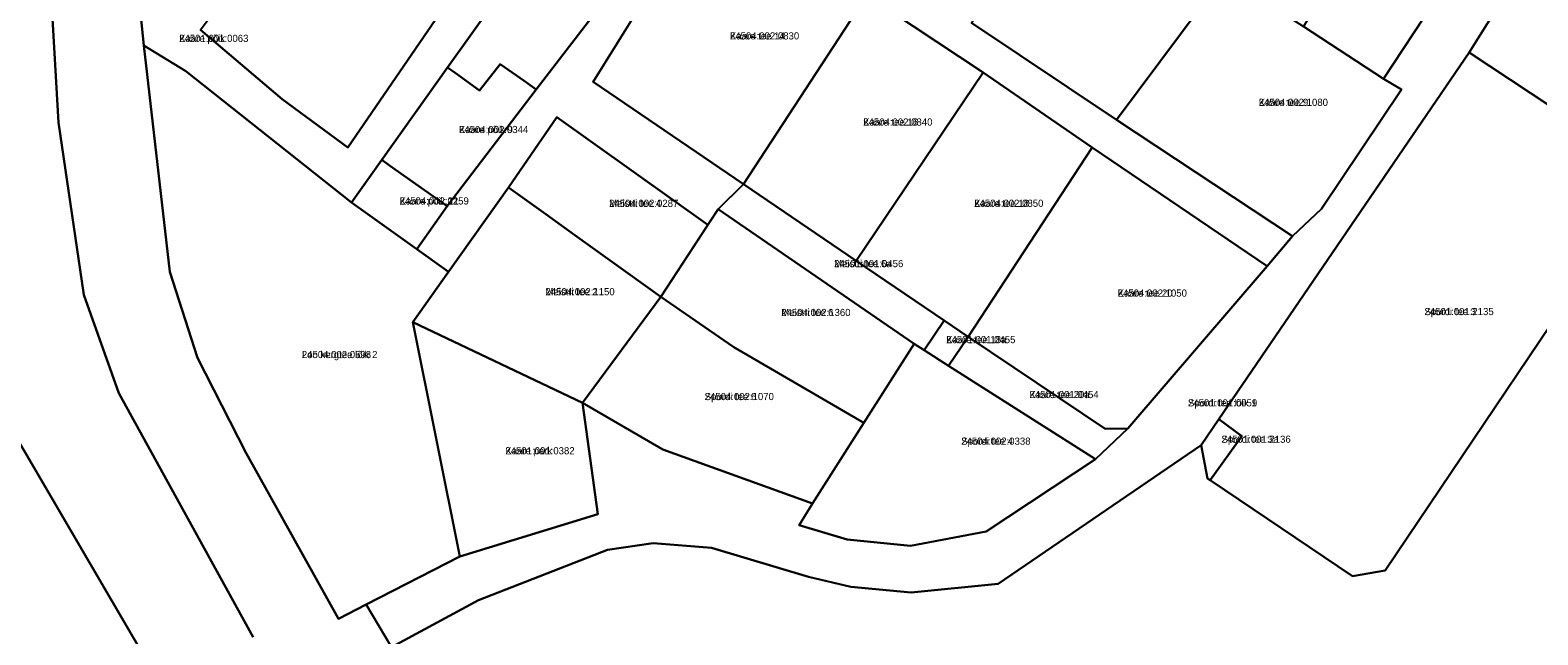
# Model space of a CAD drawing. Extents: x 551291 to 575799, y 6581704 to 6610137.
# Drawn here: x 553257.5 to 553573.3, y 6588636.2 to 6588762.8 of the extents above; entities that cross this region are included whole.
import ezdxf

# ---------------------------------------------------------------- set-up
doc = ezdxf.new("R2010")
doc.units = 0
for name, color, linetype in [('L_AADRESS', 7, 'Continuous'), ('PIIR', 7, 'Continuous'), ('TUNNUS', 7, 'Continuous')]:
    doc.layers.add(name, color=color, linetype=linetype)

msp = doc.modelspace()

# ---------------------------------------------------------------- linework, layer by layer
at = {"layer": 'PIIR'}
for points in [[(553306.96, 6589241.42), (553418.75, 6589107.11), (553465.1, 6589057.77), (553426.41, 6589023.65), (553416.94, 6589023.42), (553405.24, 6589006.54), (553386.47, 6588978.82), (553366.97, 6588950.29), (553347.5, 6588922.26), (553328.32, 6588893.48), (553310.97, 6588866.48), (553295.9, 6588840.93), (553293.3, 6588836.47), (553284.25, 6588808.2), (553281.37, 6588788.28), (553279.94, 6588773.2), (553281.34, 6588759.56), (553286.75, 6588712.18), (553292.54, 6588694.23), (553302.76, 6588674.21), (553322.1, 6588639.57), (553327.9, 6588642.55), (553333.21, 6588633.65)], [(553304.25, 6588635.73), (553276.09, 6588686.81), (553268.73, 6588707.38), (553263.45, 6588743.45), (553261.61, 6588774.94), (553261.53, 6588779.69), (553268.25, 6588819.66), (553275.1, 6588838.43), (553306.34, 6588891.77), (553312.93, 6588901.87), (553404.2, 6589032.89), (553408.34, 6589040.49), (553410.17, 6589044.79), (553406.72, 6589048.87), (553402.28, 6589051.83), (553400.8, 6589049.61), (553398.49, 6589073.95), (553395.53, 6589101.85), (553384.69, 6589115.08), (553365.54, 6589138.04), (553346.66, 6589161.17), (553325.86, 6589186.24), (553304.84, 6589211.6), (553283.11, 6589237.87)], [(553283.84, 6588627.54), (552961.52, 6589179.1), (552977.35, 6589194.37), (552972.63, 6589227.51)], [(552987.46, 6589221.09), (552996.13, 6589179.71), (553015.61, 6589144.56), (553032.97, 6589119.27), (553044.81, 6589101.34), (553061.59, 6589069.5), (553081.67, 6589036.33), (553098.19, 6589009.03), (553115.45, 6588981.63), (553133.28, 6588953.24), (553151.85, 6588924.7), (553154, 6588914.4), (553168.49, 6588890.04), (553200.1, 6588836.89), (553225.39, 6588797.38), (553242.99, 6588767.77), (553261.61, 6588774.94), (553263.45, 6588743.45), (553268.73, 6588707.38), (553276.09, 6588686.81), (553304.25, 6588635.73)], [(553586.81, 6588802.61), (553558.93, 6588758.15), (553506.49, 6588681.35), (553502.8, 6588675.9), (553460.27, 6588646.9), (553442.05, 6588645.08), (553429.4, 6588646.23), (553420.55, 6588648.38), (553400.24, 6588654.46), (553388, 6588655.43), (553378.43, 6588653.99), (553351.43, 6588643.46), (553333.21, 6588633.65), (553327.9, 6588642.55), (553347.5, 6588652.63), (553376.4, 6588661.49), (553373.17, 6588684.76), (553390, 6588675.01), (553421.37, 6588663.69), (553418.57, 6588659.2), (553428.61, 6588656.17), (553441.9, 6588654.88), (553457.72, 6588657.87), (553480.66, 6588672.97), (553487.45, 6588679.44), (553516.62, 6588713.38), (553521.94, 6588719.68), (553527.99, 6588725.41), (553544.73, 6588750.38), (553540.98, 6588752.6), (553572.58, 6588800.64)], [(553400.19, 6588791.84), (553375.41, 6588751.96), (553406.91, 6588730.55), (553401.61, 6588725.29), (553399.46, 6588722.05), (553367.85, 6588744.61), (553357.7, 6588729.84), (553345.15, 6588712.18), (553338.5, 6588716.94), (553344.85, 6588725.98), (553363.5, 6588750.35), (553377.97, 6588769.25)], [(553362.84, 6588780.12), (553344.93, 6588754.96), (553331.19, 6588735.66), (553324.82, 6588726.72), (553290.15, 6588754.19), (553281.34, 6588759.56), (553279.94, 6588773.2)], [(553293.22, 6588762.88), (553310.27, 6588748.34), (553324.04, 6588738.25), (553344.91, 6588768.66)], [(553454.68, 6588764.35), (553485.08, 6588744.02), (553521.94, 6588719.68), (553516.62, 6588713.38), (553479.95, 6588738.26), (553457.1, 6588753.9), (553432.77, 6588770.1)], [(553333.21, 6588633.65), (553351.43, 6588643.46), (553378.43, 6588653.99), (553388, 6588655.43), (553400.24, 6588654.46), (553420.55, 6588648.38), (553429.4, 6588646.23), (553442.05, 6588645.08), (553460.27, 6588646.9), (553502.8, 6588675.9), (553504.14, 6588668.94), (553504.66, 6588668.6), (553534.5, 6588648.5), (553541.34, 6588649.66), (553594.45, 6588728.54)]]:
    msp.add_lwpolyline(points, dxfattribs=at)
for points in [[(552921.6, 6588881.7), (552784.14, 6588949.64), (552783.95, 6588954.96), (552919.59, 6589073.28), (552917.17, 6589074.68), (552877.21, 6589097.76), (552961.52, 6589179.1), (553283.84, 6588627.54), (553249.24, 6588613.65), (553242.74, 6588611.05), (553050.97, 6588792.92), (552970.24, 6588851.09)], [(553572.58, 6588800.64), (553540.98, 6588752.6), (553524.22, 6588763.56), (553555.41, 6588811.64)], [(553586.81, 6588802.61), (553623.3, 6588779.03), (553593.12, 6588735.52), (553558.93, 6588758.15)], [(553485.08, 6588744.02), (553454.68, 6588764.35), (553475.29, 6588795.15), (553494.29, 6588783.09), (553507.53, 6588774.2)], [(553432.77, 6588770.1), (553406.91, 6588730.55), (553375.41, 6588751.96), (553400.19, 6588791.84)], [(553344.91, 6588768.66), (553324.04, 6588738.25), (553310.27, 6588748.34), (553293.22, 6588762.88), (553312.85, 6588789.54)], [(553362.84, 6588780.12), (553364.44, 6588778.96), (553374.81, 6588771.64), (553377.97, 6588769.25), (553363.5, 6588750.35), (553360.96, 6588752.16), (553355.97, 6588755.7), (553351.65, 6588750.19), (553346.52, 6588753.84), (553344.93, 6588754.96)], [(553507.53, 6588774.2), (553511.71, 6588771.65), (553524.22, 6588763.56), (553540.98, 6588752.6), (553544.73, 6588750.38), (553527.99, 6588725.41), (553521.94, 6588719.68), (553485.08, 6588744.02)], [(553406.91, 6588730.55), (553432.77, 6588770.1), (553457.1, 6588753.9), (553430.53, 6588714.52)], [(553281.34, 6588759.56), (553290.15, 6588754.19), (553324.82, 6588726.72), (553338.5, 6588716.94), (553345.15, 6588712.18), (553337.7, 6588701.66), (553347.5, 6588652.63), (553327.9, 6588642.55), (553322.1, 6588639.57), (553302.76, 6588674.21), (553292.54, 6588694.23), (553286.75, 6588712.18)], [(553506.49, 6588681.35), (553558.93, 6588758.15), (553593.12, 6588735.52), (553590.28, 6588731.33), (553594.45, 6588728.54), (553541.34, 6588649.66), (553534.5, 6588648.5), (553504.66, 6588668.6), (553511.28, 6588677.78)], [(553344.93, 6588754.96), (553346.52, 6588753.84), (553351.65, 6588750.19), (553355.97, 6588755.7), (553360.96, 6588752.16), (553363.5, 6588750.35), (553344.85, 6588725.98), (553343.16, 6588727.12), (553332.81, 6588734.49), (553331.19, 6588735.66)], [(553430.53, 6588714.52), (553457.1, 6588753.9), (553479.95, 6588738.26), (553453.99, 6588698.57), (553448.93, 6588701.99)], [(553357.7, 6588729.84), (553367.85, 6588744.61), (553399.46, 6588722.05), (553389.6, 6588707), (553371.6, 6588719.9), (553365.5, 6588724.27)], [(553453.99, 6588698.57), (553479.95, 6588738.26), (553516.62, 6588713.38), (553487.45, 6588679.44), (553482.71, 6588679.35)], [(553324.82, 6588726.72), (553331.19, 6588735.66), (553332.81, 6588734.49), (553343.16, 6588727.12), (553344.85, 6588725.98), (553338.5, 6588716.94)], [(553337.7, 6588701.66), (553345.15, 6588712.18), (553357.7, 6588729.84), (553365.5, 6588724.27), (553371.6, 6588719.9), (553389.6, 6588707), (553373.17, 6588684.76)], [(553442.7, 6588697.14), (553401.61, 6588725.29), (553406.91, 6588730.55), (553430.53, 6588714.52), (553448.93, 6588701.99), (553444.77, 6588695.8)], [(553442.7, 6588697.14), (553432.13, 6588680.61), (553404.91, 6588696.43), (553389.6, 6588707), (553401.61, 6588725.29)], [(553404.91, 6588696.43), (553432.13, 6588680.61), (553421.37, 6588663.69), (553390, 6588675.01), (553373.17, 6588684.76), (553389.6, 6588707)], [(553376.4, 6588661.49), (553347.5, 6588652.63), (553337.7, 6588701.66), (553373.17, 6588684.76)], [(553444.77, 6588695.8), (553448.93, 6588701.99), (553453.99, 6588698.57), (553449.89, 6588692.53)], [(553442.7, 6588697.14), (553444.77, 6588695.8), (553449.89, 6588692.53), (553480.66, 6588672.97), (553457.72, 6588657.87), (553441.9, 6588654.88), (553428.61, 6588656.17), (553418.57, 6588659.2), (553421.37, 6588663.69), (553432.13, 6588680.61)], [(553449.89, 6588692.53), (553453.99, 6588698.57), (553482.71, 6588679.35), (553487.45, 6588679.44), (553480.66, 6588672.97)], [(553502.8, 6588675.9), (553506.49, 6588681.35), (553511.28, 6588677.78), (553504.66, 6588668.6), (553504.14, 6588668.94)]]:
    msp.add_lwpolyline(points, close=True, dxfattribs=at)

# ---------------------------------------------------------------- texts
at = {"layer": 'L_AADRESS'}
for s, p in [('Kaare tee 14', (553404.09, 6588760.85)), ('Kaare põik', (553288.73, 6588760.33)), ('Kaare tee 9', (553514.84, 6588746.94)), ('Kaare tee 16', (553432, 6588742.82)), ('Kaare põik 9', (553347.34, 6588741.25)), ('Kaare põik 11', (553334.89, 6588726.3)), ('Meistri tee 4', (553378.77, 6588725.8)), ('Kaare tee 18', (553455.24, 6588725.81)), ('Meistri tee 6a', (553425.9, 6588713.18)), ('Meistri tee 2', (553365.44, 6588707.3)), ('Kaare tee 20', (553485.3, 6588707.01)), ('Meistri tee 6', (553414.84, 6588702.95)), ('Spordi tee 3', (553549.55, 6588703.14)), ('Kaare tee 18a', (553449.38, 6588697.27)), ('Loo kergtee lõik 2', (553314.42, 6588694.14)), ('Spordi tee 6', (553398.79, 6588685.35)), ('Kaare tee 20a', (553466.82, 6588685.77)), ('Spordi tee lõik 1', (553500.02, 6588684.03)), ('Spordi tee 4', (553452.54, 6588676.01)), ('Spordi tee 3a', (553507.04, 6588676.42)), ('Kaare park', (553357.05, 6588674))]:
    msp.add_text(s, height=1.5, dxfattribs=at).set_placement(p)
at = {"layer": 'TUNNUS'}
for s, p in [('24504:002:0830', (553404.09, 6588760.85)), ('24501:001:0063', (553288.73, 6588760.33)), ('24504:002:1080', (553514.84, 6588746.94)), ('24504:002:0840', (553432, 6588742.82)), ('24504:002:0344', (553347.34, 6588741.25)), ('24504:002:0259', (553334.89, 6588726.3)), ('24504:002:0287', (553378.77, 6588725.8)), ('24504:002:0850', (553455.24, 6588725.81)), ('24501:001:0456', (553425.9, 6588713.18)), ('24504:002:1150', (553365.44, 6588707.3)), ('24504:002:1050', (553485.3, 6588707.01)), ('24504:002:1360', (553414.84, 6588702.95)), ('24501:001:2135', (553549.55, 6588703.14)), ('24501:001:0455', (553449.38, 6588697.27)), ('24504:002:0598', (553314.42, 6588694.14)), ('24504:002:1070', (553398.79, 6588685.35)), ('24501:001:0454', (553466.82, 6588685.77)), ('24501:001:0059', (553500.02, 6588684.03)), ('24504:002:0338', (553452.54, 6588676.01)), ('24501:001:2136', (553507.04, 6588676.42)), ('24501:001:0382', (553357.05, 6588674))]:
    msp.add_text(s, height=1.5, dxfattribs=at).set_placement(p)

doc.saveas('drawing.dxf')
